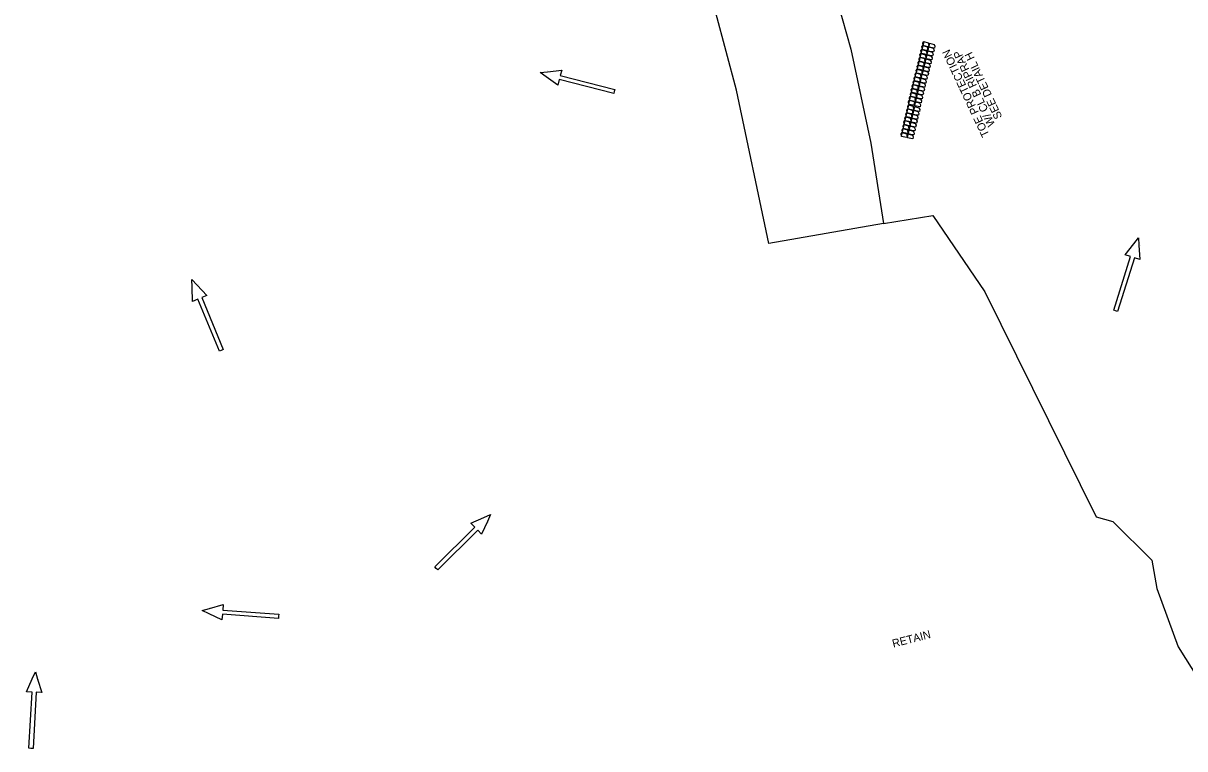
# Model space of a CAD drawing. Extents: x 465700 to 483515, y 488970 to 507540.
# Drawn here: x 477413 to 478138, y 498682 to 499135 of the extents above; entities that cross this region are included whole.
import ezdxf

# ---------------------------------------------------------------- set-up
doc = ezdxf.new("R2010")
doc.units = 0
for name, color, linetype in [('Default', 7, 'Continuous'), ('Exist Plan Preparation Drainage Flow Arrows', 7, 'Continuous'), ('Exist Plan Preparation Watershed Blue', 7, 'Continuous'), ('Prop Drainage Structure Pipe Collar Label', 7, 'Continuous'), ('Prop Erosion Embankment Toe Protection CELL', 7, 'Continuous'), ('Prop Erosion Rip Rap Pad at Outlet Label', 7, 'Continuous')]:
    doc.layers.add(name, color=color, linetype=linetype)

# ---------------------------------------------------------------- blocks, each defined once
blk = doc.blocks.new('Existing ground flow arrow')
at = {"layer": 'Default'}
blk.add_line((2.5, -4.33), (2.5, -4.33), dxfattribs=at)
blk.add_lwpolyline([(-1.29, -47.2), (-1.28, -12.53), (-4.77, -12.53), (-1.65, -4.33), (0, 0), (1.65, -4.33), (4.78, -12.53), (1.28, -12.52), (1.29, -47.19), (0, -47.2)], close=True, dxfattribs=at)

msp = doc.modelspace()

# ---------------------------------------------------------------- linework, layer by layer
at = {"layer": 'Exist Plan Preparation Watershed Blue'}
for points in [[(477913.55, 499176.64), (477929.73, 499118.92), (477942.29, 499060.3), (477950.13, 499010.07), (477878.58, 498997.57), (477858.24, 499093.41), (477832.51, 499190.03)], [(477913.55, 499176.64), (477929.73, 499118.92), (477942.29, 499060.3), (477950.13, 499010.07), (477980.89, 499015.16), (478013.47, 498967.46), (478082.89, 498826.99), (478093.27, 498823.92), (478117.63, 498799.76), (478120.94, 498782.1), (478134.26, 498745.63), (478154.98, 498712.64)]]:
    msp.add_lwpolyline(points, dxfattribs=at)
at = {"layer": 'Prop Erosion Embankment Toe Protection CELL'}
for p, q in [((477975.24, 499123.63), (477970.57, 499104.19)), ((477978.93, 499122.75), (477974.26, 499103.3)), ((477970.39, 499104.15), (477965.72, 499084.7)), ((477974.09, 499103.26), (477969.42, 499083.81)), ((477965.82, 499084.08), (477961.15, 499064.64)), ((477969.51, 499083.2), (477964.84, 499063.75))]:
    msp.add_line(p, q, dxfattribs=at)
for points in [[(477978.29, 499120.48), (477977.08, 499120.62), (477974.99, 499121.12), (477974.66, 499122.74), (477975.24, 499123.63), (477977.97, 499122.82), (477978.56, 499121.63), (477978.29, 499120.48)], [(477976.52, 499113.14), (477975.32, 499113.28), (477973.23, 499113.78), (477972.9, 499115.4), (477973.47, 499116.29), (477976.21, 499115.48), (477976.8, 499114.31), (477976.52, 499113.14)], [(477977.11, 499115.6), (477975.9, 499115.71), (477973.81, 499116.21), (477973.49, 499117.86), (477974.06, 499118.75), (477976.79, 499117.91), (477977.39, 499116.74), (477977.11, 499115.6)], [(477977.7, 499118.05), (477976.49, 499118.16), (477974.4, 499118.67), (477974.08, 499120.31), (477974.65, 499121.2), (477977.38, 499120.37), (477977.97, 499119.17), (477977.7, 499118.05)], [(477980.81, 499114.71), (477979.6, 499114.82), (477977.51, 499115.32), (477977.18, 499116.97), (477977.76, 499117.86), (477980.49, 499117.02), (477981.08, 499115.85), (477980.81, 499114.71)], [(477981.4, 499117.17), (477980.19, 499117.28), (477978.1, 499117.78), (477977.77, 499119.42), (477978.35, 499120.32), (477981.08, 499119.48), (477981.67, 499118.28), (477981.4, 499117.17)], [(477981.98, 499119.6), (477980.78, 499119.73), (477978.69, 499120.23), (477978.36, 499121.86), (477978.93, 499122.75), (477981.67, 499121.93), (477982.26, 499120.74), (477981.98, 499119.6)], [(477974.77, 499105.83), (477973.56, 499105.94), (477971.47, 499106.44), (477971.14, 499108.09), (477971.72, 499108.98), (477974.45, 499108.14), (477975.04, 499106.97), (477974.77, 499105.83)], [(477975.35, 499108.28), (477974.15, 499108.39), (477972.06, 499108.89), (477971.73, 499110.54), (477972.31, 499111.43), (477975.04, 499110.6), (477975.62, 499109.4), (477975.35, 499108.28)], [(477975.94, 499110.71), (477974.74, 499110.85), (477972.65, 499111.35), (477972.32, 499112.97), (477972.89, 499113.86), (477975.63, 499113.05), (477976.21, 499111.86), (477975.94, 499110.71)], [(477979.05, 499107.39), (477977.84, 499107.5), (477975.75, 499108.01), (477975.43, 499109.65), (477976, 499110.54), (477978.73, 499109.71), (477979.32, 499108.51), (477979.05, 499107.39)], [(477979.63, 499109.83), (477978.43, 499109.96), (477976.34, 499110.46), (477976.01, 499112.08), (477976.58, 499112.97), (477979.32, 499112.16), (477979.91, 499110.97), (477979.63, 499109.83)], [(477980.22, 499112.26), (477979.02, 499112.39), (477976.93, 499112.89), (477976.59, 499114.51), (477977.17, 499115.41), (477979.9, 499114.59), (477980.5, 499113.42), (477980.22, 499112.26)], [(477972.86, 499098.57), (477971.65, 499098.68), (477969.56, 499099.18), (477969.23, 499100.82), (477969.81, 499101.71), (477972.54, 499100.88), (477973.12, 499099.68), (477972.86, 499098.57)], [(477973.44, 499101), (477972.24, 499101.13), (477970.15, 499101.63), (477969.82, 499103.26), (477970.39, 499104.15), (477973.13, 499103.33), (477973.71, 499102.14), (477973.44, 499101)], [(477974.18, 499103.37), (477972.97, 499103.51), (477970.88, 499104.01), (477970.55, 499105.63), (477971.13, 499106.52), (477973.86, 499105.71), (477974.46, 499104.54), (477974.18, 499103.37)], [(477977.14, 499100.11), (477975.93, 499100.24), (477973.84, 499100.75), (477973.51, 499102.37), (477974.09, 499103.26), (477976.82, 499102.45), (477977.41, 499101.25), (477977.14, 499100.11)], [(477977.87, 499102.48), (477976.67, 499102.62), (477974.58, 499103.12), (477974.25, 499104.74), (477974.82, 499105.63), (477977.56, 499104.82), (477978.15, 499103.65), (477977.87, 499102.48)], [(477978.46, 499104.94), (477977.25, 499105.05), (477975.16, 499105.55), (477974.84, 499107.2), (477975.41, 499108.09), (477978.14, 499107.25), (477978.73, 499106.08), (477978.46, 499104.94)], [(477971.68, 499093.66), (477970.48, 499093.79), (477968.38, 499094.29), (477968.05, 499095.91), (477968.63, 499096.8), (477971.36, 499095.99), (477971.96, 499094.82), (477971.68, 499093.66)], [(477972.27, 499096.11), (477971.06, 499096.22), (477968.97, 499096.72), (477968.64, 499098.37), (477969.22, 499099.26), (477971.95, 499098.42), (477972.54, 499097.25), (477972.27, 499096.11)], [(477975.37, 499092.77), (477974.17, 499092.9), (477972.08, 499093.4), (477971.75, 499095.03), (477972.32, 499095.92), (477975.06, 499095.11), (477975.65, 499093.93), (477975.37, 499092.77)], [(477975.96, 499095.22), (477974.75, 499095.33), (477972.66, 499095.84), (477972.34, 499097.48), (477972.91, 499098.37), (477975.64, 499097.54), (477976.24, 499096.37), (477975.96, 499095.22)], [(477976.55, 499097.68), (477975.34, 499097.79), (477973.25, 499098.29), (477972.93, 499099.94), (477973.5, 499100.83), (477976.23, 499099.99), (477976.82, 499098.8), (477976.55, 499097.68)], [(477969.92, 499086.34), (477968.71, 499086.45), (477966.62, 499086.95), (477966.3, 499088.6), (477966.87, 499089.49), (477969.6, 499088.65), (477970.19, 499087.48), (477969.92, 499086.34)], [(477970.51, 499088.79), (477969.3, 499088.9), (477967.21, 499089.41), (477966.89, 499091.05), (477967.46, 499091.94), (477970.19, 499091.11), (477970.78, 499089.91), (477970.51, 499088.79)], [(477971.09, 499091.22), (477969.89, 499091.36), (477967.8, 499091.86), (477967.47, 499093.48), (477968.04, 499094.37), (477970.78, 499093.56), (477971.37, 499092.37), (477971.09, 499091.22)], [(477973.61, 499085.45), (477972.41, 499085.56), (477970.32, 499086.06), (477969.99, 499087.71), (477970.57, 499088.6), (477973.3, 499087.76), (477973.89, 499086.59), (477973.61, 499085.45)], [(477974.2, 499087.91), (477973, 499088.02), (477970.91, 499088.52), (477970.58, 499090.16), (477971.16, 499091.06), (477973.89, 499090.22), (477974.47, 499089.02), (477974.2, 499087.91)], [(477974.79, 499090.34), (477973.59, 499090.47), (477971.5, 499090.97), (477971.17, 499092.6), (477971.74, 499093.49), (477974.48, 499092.67), (477975.06, 499091.48), (477974.79, 499090.34)], [(477968.28, 499078.5), (477967.07, 499078.61), (477964.98, 499079.12), (477964.66, 499080.76), (477965.23, 499081.65), (477967.96, 499080.82), (477968.55, 499079.62), (477968.28, 499078.5)], [(477968.87, 499080.93), (477967.66, 499081.07), (477965.57, 499081.57), (477965.24, 499083.19), (477965.82, 499084.08), (477968.55, 499083.27), (477969.14, 499082.08), (477968.87, 499080.93)], [(477969.33, 499083.88), (477968.13, 499084.02), (477966.04, 499084.52), (477965.71, 499086.14), (477966.28, 499087.03), (477969.02, 499086.22), (477969.61, 499085.05), (477969.33, 499083.88)], [(477971.98, 499077.62), (477970.77, 499077.73), (477968.68, 499078.23), (477968.35, 499079.87), (477968.93, 499080.77), (477971.66, 499079.93), (477972.25, 499078.73), (477971.98, 499077.62)], [(477972.56, 499080.05), (477971.36, 499080.18), (477969.27, 499080.68), (477968.94, 499082.31), (477969.51, 499083.2), (477972.25, 499082.38), (477972.84, 499081.19), (477972.56, 499080.05)], [(477973.02, 499083), (477971.82, 499083.13), (477969.73, 499083.63), (477969.4, 499085.25), (477969.98, 499086.14), (477972.71, 499085.33), (477973.3, 499084.16), (477973.02, 499083)], [(477966.52, 499071.16), (477965.32, 499071.3), (477963.23, 499071.8), (477962.9, 499073.42), (477963.47, 499074.31), (477966.21, 499073.5), (477966.79, 499072.3), (477966.52, 499071.16)], [(477967.1, 499073.59), (477965.9, 499073.73), (477963.81, 499074.23), (477963.48, 499075.85), (477964.05, 499076.74), (477966.79, 499075.93), (477967.38, 499074.76), (477967.1, 499073.59)], [(477967.69, 499076.05), (477966.48, 499076.16), (477964.39, 499076.66), (477964.07, 499078.31), (477964.64, 499079.2), (477967.37, 499078.36), (477967.97, 499077.19), (477967.69, 499076.05)], [(477970.21, 499070.27), (477969.01, 499070.41), (477966.92, 499070.91), (477966.59, 499072.53), (477967.16, 499073.42), (477969.9, 499072.61), (477970.49, 499071.42), (477970.21, 499070.27)], [(477970.8, 499072.71), (477969.6, 499072.84), (477967.51, 499073.34), (477967.17, 499074.96), (477967.75, 499075.85), (477970.48, 499075.04), (477971.08, 499073.87), (477970.8, 499072.71)], [(477971.39, 499075.16), (477970.18, 499075.27), (477968.09, 499075.77), (477967.76, 499077.42), (477968.34, 499078.31), (477971.07, 499077.47), (477971.66, 499076.3), (477971.39, 499075.16)], [(477964.76, 499063.82), (477963.55, 499063.96), (477961.46, 499064.46), (477961.13, 499066.08), (477961.71, 499066.97), (477964.44, 499066.16), (477965.04, 499064.99), (477964.76, 499063.82)], [(477965.34, 499066.28), (477964.14, 499066.39), (477962.05, 499066.89), (477961.72, 499068.53), (477962.3, 499069.43), (477965.03, 499068.59), (477965.62, 499067.42), (477965.34, 499066.28)], [(477965.93, 499068.73), (477964.73, 499068.84), (477962.64, 499069.34), (477962.31, 499070.99), (477962.89, 499071.88), (477965.62, 499071.04), (477966.2, 499069.85), (477965.93, 499068.73)], [(477968.45, 499062.93), (477967.25, 499063.07), (477965.16, 499063.57), (477964.83, 499065.19), (477965.4, 499066.08), (477968.14, 499065.27), (477968.73, 499064.1), (477968.45, 499062.93)], [(477969.04, 499065.39), (477967.83, 499065.5), (477965.74, 499066), (477965.42, 499067.65), (477965.99, 499068.54), (477968.72, 499067.7), (477969.31, 499066.53), (477969.04, 499065.39)], [(477969.63, 499067.84), (477968.42, 499067.95), (477966.33, 499068.46), (477966.01, 499070.1), (477966.58, 499070.99), (477969.31, 499070.16), (477969.9, 499068.96), (477969.63, 499067.84)]]:
    msp.add_lwpolyline(points, dxfattribs=at)

# ---------------------------------------------------------------- block references
at = {"layer": 'Exist Plan Preparation Drainage Flow Arrows'}
for p, xscale, yscale, rotation in [((477735.64, 499104.33), 1.0124070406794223, 1.0124070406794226, 75.64485211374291), ((478109.42, 499001.16), 1.0124070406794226, 1.0124070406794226, -17.40127002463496), ((477518.23, 498975.02), 1.012407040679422, 1.0124070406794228, 22.497364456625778), ((477704.75, 498828.37), 1.0124070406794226, 1.012407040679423, -45.284478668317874), ((477524.67, 498768.36), 1.0124070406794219, 1.0124070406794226, 85.72151958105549), ((477420.39, 498730.06), 1.012407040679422, 1.0124070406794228, -3.297257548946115)]:
    msp.add_blockref('Existing ground flow arrow', p, dxfattribs=dict(at, xscale=xscale, yscale=yscale, rotation=rotation))

# ---------------------------------------------------------------- texts
at = {"layer": 'Prop Drainage Structure Pipe Collar Label'}
msp.add_text('RETAIN', height=5, rotation=14.35092, dxfattribs=at).set_placement((477956.28, 498745.27))
at = {"layer": 'Prop Erosion Rip Rap Pad at Outlet Label'}
for s, p in [('TOE PROTECTION', (478016.42, 499065.45)), ('W/ CL B RIPRAP', (478019.97, 499071.99)), ('SEE DETAIL H', (478024.41, 499076.65))]:
    msp.add_text(s, height=5, rotation=115.17056, dxfattribs=at).set_placement(p)

doc.saveas('drawing.dxf')
